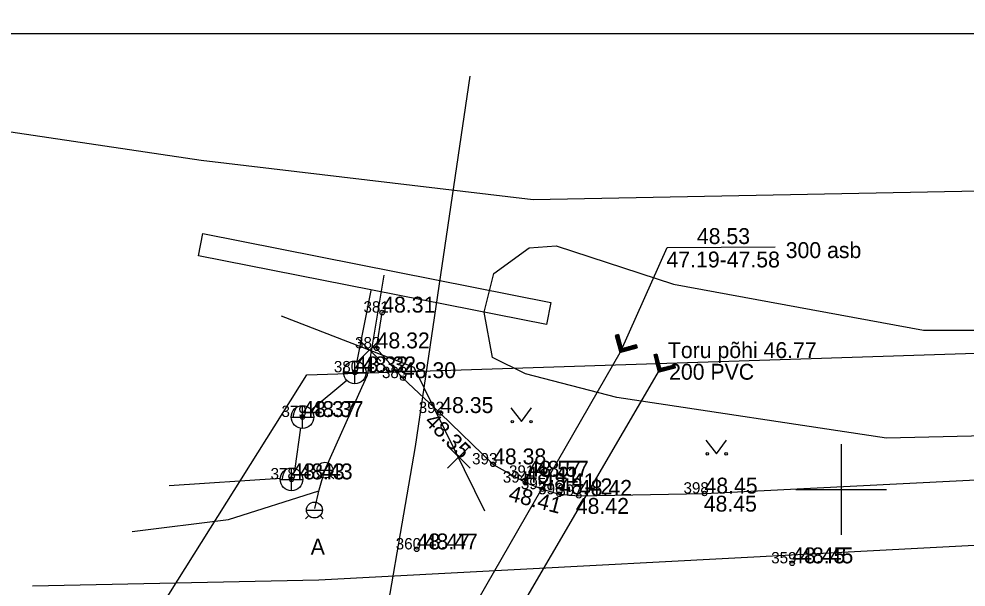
# Model space of a CAD drawing. Extents: x 640876 to 641418, y 6455595 to 6456085.
# Drawn here: x 641063.77 to 641105.51, y 6455995.7 to 6456020.73 of the extents above; entities that cross this region are included whole.
import ezdxf

# ---------------------------------------------------------------- set-up
doc = ezdxf.new("R2010")
doc.units = 0
for name, color, linetype in [('HALJASTUS', 7, 'Continuous'), ('KKAEV', 7, 'Continuous'), ('KORGUS', 7, 'Continuous'), ('KPKAABEL', 7, 'Continuous'), ('KTRASS', 7, 'Continuous'), ('MOOTKORG', 7, 'Continuous'), ('MOOTMPUNKT', 7, 'Continuous'), ('MOOTNR', 7, 'Continuous'), ('MOOTPIIR', 7, 'Continuous'), ('PIIR', 7, 'Continuous'), ('SITRASS', 7, 'Continuous'), ('SKTRASS', 7, 'Continuous'), ('TEE', 7, 'Continuous'), ('TRUUP', 7, 'Continuous'), ('VEEKOGU', 7, 'Continuous'), ('VKAEV', 7, 'Continuous'), ('VORK', 7, 'Continuous'), ('VORMISTUS', 7, 'Continuous'), ('VTRASS', 7, 'Continuous')]:
    doc.layers.add(name, color=color, linetype=linetype)

msp = doc.modelspace()

# ---------------------------------------------------------------- linework, layer by layer
at = {"layer": 'HALJASTUS'}
for p, q in [((641085.447, 6456003.599), (641085.91, 6456002.992)), ((641085.91, 6456002.992), (641086.356, 6456003.599)), ((641094.042, 6456002.179), (641094.506, 6456001.572)), ((641094.506, 6456001.572), (641094.951, 6456002.179))]:
    msp.add_line(p, q, dxfattribs=at)
for centre in [(641085.509, 6456002.992), (641086.338, 6456002.992), (641094.105, 6456001.572), (641094.934, 6456001.572)]:
    msp.add_circle(centre, 0.055, dxfattribs=at)
at = {"layer": 'KKAEV'}
for p, q in [((641078.572, 6456004.662), (641078.572, 6456005.662)), ((641078.072, 6456005.162), (641079.072, 6456005.162)), ((641076.264, 6456002.694), (641076.264, 6456003.694)), ((641075.764, 6456003.194), (641076.764, 6456003.194)), ((641075.782, 6455999.947), (641075.782, 6456000.947)), ((641075.282, 6456000.447), (641076.282, 6456000.447))]:
    msp.add_line(p, q, dxfattribs=at)
for centre in [(641078.572, 6456005.162), (641076.264, 6456003.194), (641075.782, 6456000.447)]:
    msp.add_circle(centre, 0.5, dxfattribs=at)
at = {"layer": 'KORGUS'}
for centre in [(641078.572, 6456005.162), (641076.264, 6456003.194), (641082.336, 6456003.369), (641075.782, 6456000.447), (641086.093, 6456000.303), (641086.191, 6456000.565), (641093.981, 6455999.821), (641088.445, 6455999.722), (641081.299, 6455997.362), (641097.846, 6455996.747)]:
    msp.add_circle(centre, 0.1, dxfattribs=at)
at = {"layer": 'KPKAABEL'}
msp.add_lwpolyline([(641068.476, 6455977.159), (641079.463, 6455991.588), (641081.251, 6456001.896), (641083.656, 6456018.212)], dxfattribs=at)
at = {"layer": 'KTRASS'}
for points in [[(641078.668, 6456005.652), (641079.286, 6456008.76)], [(641076.646, 6456003.517), (641078.215, 6456004.811)], [(641075.943, 6456000.919), (641076.193, 6456002.71)], [(641075.284, 6456000.489), (641070.39, 6456000.162)]]:
    msp.add_lwpolyline(points, dxfattribs=at)
at = {"layer": 'MOOTMPUNKT'}
for centre in [(641079.778, 6456007.794), (641079.531, 6456006.218), (641078.572, 6456005.162), (641080.691, 6456004.907), (641076.264, 6456003.194), (641082.336, 6456003.369), (641084.664, 6456001.107), (641075.782, 6456000.447), (641086.093, 6456000.303), (641086.191, 6456000.565), (641086.838, 6456000.014), (641093.981, 6455999.821), (641087.575, 6455999.79), (641088.445, 6455999.722), (641081.299, 6455997.362), (641097.846, 6455996.747)]:
    msp.add_circle(centre, 0.1, dxfattribs=at)
at = {"layer": 'MOOTPIIR'}
msp.add_lwpolyline([(641060.916, 6455895.936), (641100.061, 6455950.482), (641099.586, 6455952.159), (641069.132, 6455984.035), (641066.132, 6455988.623), (641076.463, 6456005.049), (641230.642, 6456010.048), (641237.36, 6455995.24), (641237.24, 6455992.81), (641236.258, 6455990.888), (641229.041, 6455971.315), (641203.026, 6455909.57), (641225.257, 6455906.847), (641239.512, 6455898.491), (641200.195, 6455851.697), (641192.016, 6455859.099), (641169.785, 6455829.138), (641192.025, 6455807.568), (641252.96, 6455758.075), (641231.388, 6455736.74), (641191.474, 6455775.975), (641152.419, 6455787.914), (641136.351, 6455788.307), (641049.066, 6455856.043)], dxfattribs=at)
at = {"layer": 'PIIR'}
msp.add_lwpolyline([(640981.25, 6456014.49), (641018.11, 6456020.73), (641048.89, 6456017.91), (641071.8, 6456014.51), (641086.43, 6456012.78), (641194.48, 6456014.88), (641224.33, 6456016.64), (641234.96, 6456017.83), (641241.97, 6456004.88), (641237.36, 6455995.24), (641222.58, 6455998.61), (641084.84, 6455991.92), (641061.51, 6455993.34), (640998.61, 6455989.99), (640969.54, 6455988.44)], close=True, dxfattribs=at)
at = {"layer": 'SITRASS'}
for p, q in [((641078.72, 6456006.637), (641079.71, 6456005.647)), ((641078.72, 6456005.647), (641079.71, 6456006.637)), ((641082.66, 6456001.923), (641083.65, 6456000.933)), ((641082.66, 6456000.933), (641083.65, 6456001.923))]:
    msp.add_line(p, q, dxfattribs=at)
for points in [[(641081.189, 6456005.38), (641075.335, 6456007.636)], [(641084.299, 6455999.051), (641081.189, 6456005.38)]]:
    msp.add_lwpolyline(points, dxfattribs=at)
at = {"layer": 'SKTRASS'}
for p, q in [((641091.887, 6456005.961), (641091.748, 6456005.927)), ((641091.748, 6456005.927), (641091.934, 6456005.171)), ((641091.777, 6456005.934), (641091.762, 6456005.87)), ((641091.804, 6456005.941), (641091.776, 6456005.816)), ((641091.831, 6456005.947), (641091.789, 6456005.762)), ((641091.858, 6456005.954), (641091.802, 6456005.709)), ((641091.886, 6456005.961), (641091.815, 6456005.655)), ((641091.817, 6456005.944), (641091.986, 6456005.257)), ((641091.899, 6456005.909), (641091.829, 6456005.601)), ((641091.913, 6456005.855), (641091.842, 6456005.547)), ((641091.926, 6456005.801), (641091.855, 6456005.493)), ((641091.939, 6456005.747), (641091.868, 6456005.439)), ((641091.887, 6456005.961), (641092.039, 6456005.343)), ((641091.952, 6456005.693), (641091.882, 6456005.385)), ((641091.966, 6456005.639), (641091.895, 6456005.331)), ((641091.979, 6456005.585), (641091.908, 6456005.277)), ((641091.992, 6456005.531), (641091.922, 6456005.223)), ((641091.934, 6456005.171), (641092.69, 6456005.357)), ((641092.006, 6456005.477), (641091.935, 6456005.171)), ((641092.019, 6456005.423), (641091.963, 6456005.178)), ((641091.986, 6456005.257), (641092.673, 6456005.426)), ((641092.032, 6456005.37), (641091.99, 6456005.185)), ((641092.053, 6456005.347), (641092.017, 6456005.192)), ((641092.039, 6456005.343), (641092.656, 6456005.495)), ((641092.08, 6456005.354), (641092.044, 6456005.198)), ((641092.107, 6456005.36), (641092.071, 6456005.205)), ((641092.134, 6456005.367), (641092.099, 6456005.212)), ((641092.161, 6456005.374), (641092.126, 6456005.218)), ((641092.189, 6456005.38), (641092.153, 6456005.225)), ((641092.216, 6456005.387), (641092.18, 6456005.232)), ((641092.243, 6456005.394), (641092.207, 6456005.238)), ((641092.27, 6456005.4), (641092.234, 6456005.245)), ((641092.297, 6456005.407), (641092.262, 6456005.252)), ((641092.324, 6456005.414), (641092.289, 6456005.258)), ((641092.352, 6456005.421), (641092.316, 6456005.265)), ((641092.379, 6456005.427), (641092.343, 6456005.272)), ((641092.406, 6456005.434), (641092.37, 6456005.279)), ((641092.433, 6456005.441), (641092.398, 6456005.285)), ((641092.46, 6456005.447), (641092.425, 6456005.292)), ((641092.488, 6456005.454), (641092.452, 6456005.299)), ((641092.515, 6456005.461), (641092.479, 6456005.305)), ((641092.542, 6456005.467), (641092.506, 6456005.312)), ((641092.569, 6456005.474), (641092.533, 6456005.319)), ((641092.596, 6456005.481), (641092.561, 6456005.325)), ((641092.623, 6456005.487), (641092.588, 6456005.332)), ((641092.651, 6456005.494), (641092.615, 6456005.339)), ((641092.667, 6456005.452), (641092.642, 6456005.345)), ((641092.656, 6456005.495), (641092.69, 6456005.357)), ((641092.68, 6456005.398), (641092.669, 6456005.352))]:
    msp.add_line(p, q, dxfattribs=at)
msp.add_lwpolyline([(641091.986, 6456005.257), (641077.702, 6455980.813)], dxfattribs=at)
at = {"layer": 'TEE'}
for points in [[(641082.336, 6456003.369), (641080.691, 6456004.907), (641079.531, 6456006.218), (641079.778, 6456007.794)], [(641082.336, 6456003.369), (641084.664, 6456001.107), (641086.093, 6456000.303), (641086.838, 6456000.014), (641087.575, 6455999.79), (641088.445, 6455999.722), (641093.981, 6455999.821), (641114.127, 6456000.844), (641114.356, 6456001.115)]]:
    msp.add_lwpolyline(points, dxfattribs=at)
at = {"layer": 'TRUUP'}
for p, q in [((641090.188, 6456006.83), (641090.051, 6456006.792)), ((641090.051, 6456006.792), (641090.257, 6456006.042)), ((641090.079, 6456006.8), (641090.066, 6456006.736)), ((641090.106, 6456006.807), (641090.081, 6456006.682)), ((641090.133, 6456006.815), (641090.096, 6456006.629)), ((641090.16, 6456006.822), (641090.111, 6456006.575)), ((641090.12, 6456006.811), (641090.307, 6456006.129)), ((641090.187, 6456006.83), (641090.125, 6456006.522)), ((641090.202, 6456006.778), (641090.14, 6456006.468)), ((641090.217, 6456006.725), (641090.155, 6456006.415)), ((641090.232, 6456006.671), (641090.17, 6456006.361)), ((641090.247, 6456006.618), (641090.184, 6456006.307)), ((641090.188, 6456006.83), (641090.357, 6456006.217)), ((641090.261, 6456006.564), (641090.199, 6456006.254)), ((641090.276, 6456006.511), (641090.214, 6456006.2)), ((641090.291, 6456006.457), (641090.229, 6456006.147)), ((641090.306, 6456006.403), (641090.243, 6456006.093)), ((641090.257, 6456006.042), (641091.008, 6456006.248)), ((641090.32, 6456006.35), (641090.258, 6456006.042)), ((641090.335, 6456006.296), (641090.285, 6456006.05)), ((641090.307, 6456006.129), (641090.989, 6456006.317)), ((641090.35, 6456006.243), (641090.312, 6456006.057)), ((641090.371, 6456006.221), (641090.339, 6456006.064)), ((641090.357, 6456006.217), (641090.97, 6456006.386)), ((641090.398, 6456006.228), (641090.366, 6456006.072)), ((641090.425, 6456006.236), (641090.393, 6456006.079)), ((641090.452, 6456006.243), (641090.42, 6456006.087)), ((641090.479, 6456006.25), (641090.447, 6456006.094)), ((641090.506, 6456006.258), (641090.474, 6456006.102)), ((641090.533, 6456006.265), (641090.501, 6456006.109)), ((641090.56, 6456006.273), (641090.528, 6456006.116)), ((641090.587, 6456006.28), (641090.555, 6456006.124)), ((641090.614, 6456006.288), (641090.582, 6456006.131)), ((641090.641, 6456006.295), (641090.609, 6456006.139)), ((641090.668, 6456006.302), (641090.636, 6456006.146)), ((641090.695, 6456006.31), (641090.663, 6456006.153)), ((641090.722, 6456006.317), (641090.69, 6456006.161)), ((641090.749, 6456006.325), (641090.717, 6456006.168)), ((641090.776, 6456006.332), (641090.744, 6456006.176)), ((641090.803, 6456006.339), (641090.771, 6456006.183)), ((641090.83, 6456006.347), (641090.798, 6456006.191)), ((641090.857, 6456006.354), (641090.825, 6456006.198)), ((641090.884, 6456006.362), (641090.852, 6456006.205)), ((641090.911, 6456006.369), (641090.879, 6456006.213)), ((641090.938, 6456006.377), (641090.906, 6456006.22)), ((641090.965, 6456006.384), (641090.933, 6456006.228)), ((641090.982, 6456006.343), (641090.96, 6456006.235)), ((641090.97, 6456006.386), (641091.008, 6456006.248)), ((641090.997, 6456006.289), (641090.987, 6456006.243))]:
    msp.add_line(p, q, dxfattribs=at)
for points in [[(641071.879, 6456011.282), (641087.213, 6456008.244), (641087.019, 6456007.263), (641071.685, 6456010.301), (641071.879, 6456011.282)], [(641090.307, 6456006.129), (641092.333, 6456010.659), (641097.097, 6456010.685)], [(641090.307, 6456006.129), (641075.531, 6455980.433)]]:
    msp.add_lwpolyline(points, dxfattribs=at)
at = {"layer": 'VEEKOGU'}
msp.add_lwpolyline([(641139.156, 6456004.288), (641122.94, 6456003.612), (641113.848, 6456002.539), (641102.002, 6456002.261), (641090.12, 6456004.057), (641086.086, 6456005.103), (641084.645, 6456005.811), (641084.269, 6456007.81), (641084.697, 6456009.512), (641086.26, 6456010.646), (641087.438, 6456010.728), (641092.614, 6456009.053), (641103.632, 6456007.017), (641117.202, 6456007.024), (641129.494, 6456007.757), (641140.506, 6456009.297)], dxfattribs=at)
at = {"layer": 'VKAEV'}
for p, q in [((641076.905, 6456000.854), (641077.605, 6456000.854)), ((641077.007, 6456000.606), (641076.868, 6456000.467)), ((641077.502, 6456000.606), (641077.642, 6456000.467)), ((641076.44, 6455999.096), (641077.14, 6455999.096)), ((641076.542, 6455998.849), (641076.403, 6455998.709)), ((641077.037, 6455998.849), (641077.177, 6455998.709))]:
    msp.add_line(p, q, dxfattribs=at)
for centre in [(641077.255, 6456000.854), (641076.79, 6455999.096)]:
    msp.add_circle(centre, 0.35, dxfattribs=at)
at = {"layer": 'VORK'}
for p, q in [((641100, 6456002), (641100, 6455998)), ((641098, 6456000), (641102, 6456000))]:
    msp.add_line(p, q, dxfattribs=at)
at = {"layer": 'VORMISTUS'}
msp.add_line((641035.115, 6456020.09), (641256.302, 6456020.09), dxfattribs=at)
at = {"layer": 'VTRASS'}
for points in [[(641076.806, 6455999.163), (641077.006, 6455999.984), (641077.255, 6456000.854), (641078.886, 6456004.499), (641079.13, 6456005.044), (641079.857, 6456009.441)], [(641064.363, 6455995.75), (641076.979, 6455996.021), (641104.204, 6455997.462), (641127.864, 6455998.715), (641152.811, 6456000.037), (641188.143, 6456001.908), (641203.655, 6456002.73), (641225.036, 6456004.365)], [(641068.753, 6455998.156), (641073.007, 6455998.681), (641076.98, 6455999.949)]]:
    msp.add_lwpolyline(points, dxfattribs=at)

# ---------------------------------------------------------------- texts
at = {"layer": 'KORGUS'}
for s, p in [('48.32', (641078.922, 6456005.162)), ('48.37', (641076.614, 6456003.194)), ('48.43', (641076.132, 6456000.447)), ('48.57', (641086.541, 6456000.565)), ('48.42', (641088.31, 6455998.927)), ('48.45', (641093.948, 6455999.026)), ('48.47', (641081.649, 6455997.362)), ('48.45', (641098.196, 6455996.747))]:
    msp.add_text(s, height=0.7, dxfattribs=at).set_placement(p)
for s, rotation, p in [('48.35', 314.9845, (641081.603, 6456002.957)), ('48.41', 345.3408, (641085.303, 6455999.52))]:
    msp.add_text(s, height=0.7, rotation=rotation, dxfattribs=at).set_placement(p)
at = {"layer": 'MOOTKORG'}
for s, p in [('48.31', (641079.778, 6456007.794)), ('48.32', (641079.531, 6456006.218)), ('48.32', (641078.572, 6456005.162)), ('48.30', (641080.691, 6456004.907)), ('48.35', (641082.336, 6456003.369)), ('48.37', (641076.264, 6456003.194)), ('48.38', (641084.664, 6456001.107)), ('48.43', (641075.782, 6456000.447)), ('48.57', (641086.191, 6456000.565)), ('48.41', (641086.093, 6456000.303)), ('48.41', (641086.838, 6456000.014)), ('48.42', (641087.575, 6455999.79)), ('48.42', (641088.445, 6455999.722)), ('48.45', (641093.981, 6455999.821)), ('48.47', (641081.299, 6455997.362)), ('48.45', (641097.846, 6455996.747))]:
    msp.add_text(s, height=0.7, dxfattribs=at).set_placement(p)
at = {"layer": 'MOOTNR'}
for s, p in [('381', (641078.953, 6456007.794)), ('382', (641078.581, 6456006.218)), ('380', (641077.647, 6456005.162)), ('383', (641079.766, 6456004.907)), ('379', (641075.339, 6456003.194)), ('392', (641081.386, 6456003.369)), ('393', (641083.739, 6456001.107)), ('378', (641074.857, 6456000.447)), ('394', (641085.093, 6456000.303)), ('391', (641085.366, 6456000.565)), ('395', (641085.888, 6456000.014)), ('398', (641093.056, 6455999.821)), ('396', (641086.65, 6455999.79)), ('397', (641087.495, 6455999.722)), ('360', (641080.374, 6455997.362)), ('359', (641096.921, 6455996.747))]:
    msp.add_text(s, height=0.5, dxfattribs=at).set_placement(p)
at = {"layer": 'SKTRASS'}
for s, p in [('Toru põhi 46.77', (641092.369, 6456005.79)), ('200 PVC', (641092.421, 6456004.837))]:
    msp.add_text(s, height=0.7, dxfattribs=at).set_placement(p)
at = {"layer": 'TEE'}
msp.add_text('A', height=0.7, dxfattribs=at).set_placement((641076.627, 6455997.133))
at = {"layer": 'TRUUP'}
for s, p in [('48.53', (641093.646, 6456010.814)), ('300 asb', (641097.56, 6456010.195)), ('47.19-47.58', (641092.307, 6456009.783))]:
    msp.add_text(s, height=0.7, dxfattribs=at).set_placement(p)

doc.saveas('drawing.dxf')
